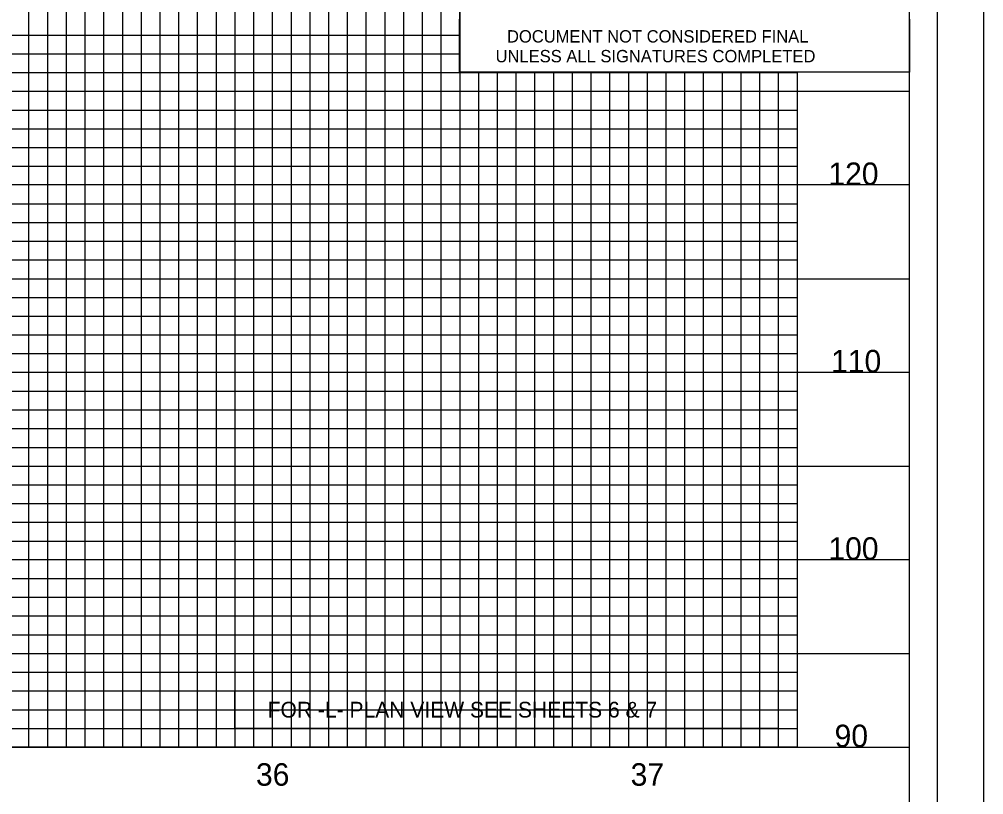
# Model space of a CAD drawing. Extents: x 2113763 to 2114783, y 714280 to 714940.
# Drawn here: x 2114525.3 to 2114782.6, y 714612.6 to 714819.5 of the extents above; entities that cross this region are included whole.
import ezdxf

# ---------------------------------------------------------------- set-up
doc = ezdxf.new("R2010")
doc.units = 0
for name, color, linetype in [('Exist Vertical Profile Horizontal Axis Label Major', 7, 'Continuous'), ('Exist Vertical Profile Vertical Axis Label', 7, 'Continuous'), ('Prop Grid Mask', 7, 'Continuous'), ('Prop PFL Text', 7, 'Continuous'), ('Sheet Cutting Line CELL', 7, 'Continuous'), ('Sheet Layout Profile Border Port 1', 7, 'Continuous'), ('Sheet Plot Border Inside CELL', 7, 'Continuous'), ('Sheet Plot Border Outside CELL', 7, 'Continuous'), ('Sheet Profile CELL', 7, 'Continuous'), ('Sheet Profile Grid Major CELL', 7, 'Continuous'), ('Sheet Profile Grid Middle CELL', 7, 'Continuous'), ('Sheet Profile Grid Minor CELL', 7, 'Continuous'), ('Sheet Sticker Exception Certification CELL', 7, 'Continuous')]:
    doc.layers.add(name, color=color, linetype=linetype)

msp = doc.modelspace()

# ---------------------------------------------------------------- linework, layer by layer
at = {"layer": 'Exist Vertical Profile Vertical Axis Label'}
msp.add_lwpolyline([(2114582.76, 714640.29), (2114727.76, 714640.29), (2114727.76, 714630.29), (2114582.76, 714630.29)], close=True, dxfattribs=at)
at = {"layer": 'Prop Grid Mask'}
msp.add_lwpolyline([(2114582.76, 714640.29), (2114727.76, 714640.29), (2114727.76, 714630.29), (2114582.76, 714630.29)], close=True, dxfattribs=at)
at = {"layer": 'Sheet Cutting Line CELL'}
msp.add_line((2114782.56, 714280.29), (2114782.56, 714940.29), dxfattribs=at)
at = {"layer": 'Sheet Layout Profile Border Port 1'}
msp.add_lwpolyline([(2113892.76, 714925.29), (2114642.73, 714925.29), (2114642.73, 714805.41), (2114732.76, 714805.29), (2114732.76, 714625.29), (2113892.76, 714625.29)], close=True, dxfattribs=at)
at = {"layer": 'Sheet Plot Border Inside CELL'}
msp.add_lwpolyline([(2113770.36, 714293.76), (2114770.26, 714293.76), (2114770.26, 714926.82), (2113770.36, 714926.82)], close=True, dxfattribs=at)
at = {"layer": 'Sheet Plot Border Outside CELL'}
msp.add_lwpolyline([(2113762.56, 714280.29), (2114782.56, 714280.29), (2114782.56, 714940.29), (2113762.56, 714940.29)], close=True, dxfattribs=at)
at = {"layer": 'Sheet Profile CELL'}
msp.add_line((2113862.76, 714625.29), (2114762.76, 714625.29), dxfattribs=at)
msp.add_lwpolyline([(2114762.76, 714925.29), (2113862.76, 714925.29), (2113862.76, 714295.29), (2114762.76, 714295.29)], close=True, dxfattribs=at)
at = {"layer": 'Sheet Profile Grid Major CELL'}
for p, q in [((2114542.76, 714925.29), (2114542.76, 714625.29)), ((2114567.76, 714925.29), (2114567.76, 714625.29)), ((2114592.76, 714925.29), (2114592.76, 714625.29)), ((2114617.76, 714925.29), (2114617.76, 714625.29)), ((2114642.76, 714925.29), (2114642.76, 714625.29)), ((2114667.76, 714805.41), (2114667.76, 714625.29)), ((2114692.76, 714805.41), (2114692.76, 714625.29)), ((2114717.76, 714805.41), (2114717.76, 714625.29)), ((2114732.76, 714805.41), (2114732.76, 714625.29)), ((2113862.76, 714800.29), (2114762.76, 714800.29)), ((2114762.76, 714775.29), (2113862.76, 714775.29)), ((2113862.76, 714750.29), (2114762.76, 714750.29)), ((2114762.76, 714725.29), (2113862.76, 714725.29)), ((2113862.76, 714700.29), (2114762.76, 714700.29)), ((2114762.76, 714675.29), (2113862.76, 714675.29)), ((2113862.76, 714650.29), (2114762.76, 714650.29))]:
    msp.add_line(p, q, dxfattribs=at)
at = {"layer": 'Sheet Profile Grid Middle CELL'}
for p, q in [((2113892.76, 714815.29), (2114642.76, 714815.29)), ((2113892.76, 714810.29), (2114642.76, 714810.29)), ((2113892.76, 714805.29), (2114732.76, 714805.29)), ((2113892.76, 714795.29), (2114732.76, 714795.29)), ((2113892.76, 714790.29), (2114732.76, 714790.29)), ((2113892.76, 714785.29), (2114732.76, 714785.29)), ((2113892.76, 714780.29), (2114732.76, 714780.29)), ((2113892.76, 714770.29), (2114732.76, 714770.29)), ((2113892.76, 714765.29), (2114732.76, 714765.29)), ((2113892.76, 714760.29), (2114732.76, 714760.29)), ((2113892.76, 714755.29), (2114732.76, 714755.29)), ((2113892.76, 714745.29), (2114732.76, 714745.29)), ((2113892.76, 714740.29), (2114732.76, 714740.29)), ((2113892.76, 714735.29), (2114732.76, 714735.29)), ((2113892.76, 714730.29), (2114732.76, 714730.29)), ((2113892.76, 714720.29), (2114732.76, 714720.29)), ((2113892.76, 714715.29), (2114732.76, 714715.29)), ((2113892.76, 714710.29), (2114732.76, 714710.29)), ((2113892.76, 714705.29), (2114732.76, 714705.29)), ((2113892.76, 714695.29), (2114732.76, 714695.29)), ((2113892.76, 714690.29), (2114732.76, 714690.29)), ((2113892.76, 714685.29), (2114732.76, 714685.29)), ((2113892.76, 714680.29), (2114732.76, 714680.29)), ((2113892.76, 714670.29), (2114732.76, 714670.29)), ((2113892.76, 714665.29), (2114732.76, 714665.29)), ((2113892.76, 714660.29), (2114732.76, 714660.29)), ((2113892.76, 714655.29), (2114732.76, 714655.29)), ((2113892.76, 714645.29), (2114732.76, 714645.29)), ((2113892.76, 714640.29), (2114732.76, 714640.29)), ((2113892.76, 714635.29), (2114732.76, 714635.29)), ((2113892.76, 714630.29), (2114732.76, 714630.29))]:
    msp.add_line(p, q, dxfattribs=at)
msp.add_lwpolyline([(2114657.76, 714790.29), (2114732.76, 714790.29)], dxfattribs=at)
at = {"layer": 'Sheet Profile Grid Minor CELL'}
for p, q in [((2114527.76, 714925.29), (2114527.76, 714625.29)), ((2114532.76, 714925.29), (2114532.76, 714625.29)), ((2114537.76, 714925.29), (2114537.76, 714625.29)), ((2114547.76, 714925.29), (2114547.76, 714625.29)), ((2114552.76, 714925.29), (2114552.76, 714625.29)), ((2114557.76, 714925.29), (2114557.76, 714625.29)), ((2114562.76, 714925.29), (2114562.76, 714625.29)), ((2114572.76, 714925.29), (2114572.76, 714625.29)), ((2114577.76, 714925.29), (2114577.76, 714625.29)), ((2114582.76, 714925.29), (2114582.76, 714625.29)), ((2114587.76, 714925.29), (2114587.76, 714625.29)), ((2114597.76, 714925.29), (2114597.76, 714625.29)), ((2114602.76, 714925.29), (2114602.76, 714625.29)), ((2114607.76, 714925.29), (2114607.76, 714625.29)), ((2114612.76, 714925.29), (2114612.76, 714625.29)), ((2114622.76, 714925.29), (2114622.76, 714625.29)), ((2114627.76, 714925.29), (2114627.76, 714625.29)), ((2114632.76, 714925.29), (2114632.76, 714625.29)), ((2114637.76, 714925.29), (2114637.76, 714625.29)), ((2114647.76, 714805.41), (2114647.76, 714625.29)), ((2114652.76, 714805.41), (2114652.76, 714625.29)), ((2114657.76, 714805.41), (2114657.76, 714625.29)), ((2114662.76, 714805.41), (2114662.76, 714625.29)), ((2114672.76, 714805.41), (2114672.76, 714625.29)), ((2114677.76, 714805.41), (2114677.76, 714625.29)), ((2114682.76, 714805.41), (2114682.76, 714625.29)), ((2114687.76, 714805.41), (2114687.76, 714625.29)), ((2114697.76, 714805.41), (2114697.76, 714625.29)), ((2114702.76, 714805.41), (2114702.76, 714625.29)), ((2114707.76, 714805.41), (2114707.76, 714625.29)), ((2114712.76, 714805.41), (2114712.76, 714625.29)), ((2114722.76, 714805.41), (2114722.76, 714625.29)), ((2114727.76, 714805.41), (2114727.76, 714625.29))]:
    msp.add_line(p, q, dxfattribs=at)
at = {"layer": 'Sheet Sticker Exception Certification CELL'}
for p, q in [((2114642.73, 714805.41), (2114642.73, 714819.51)), ((2114762.76, 714819.5), (2114762.76, 714805.4)), ((2114762.76, 714805.41), (2114642.73, 714805.41))]:
    msp.add_line(p, q, dxfattribs=at)

# ---------------------------------------------------------------- texts
at = {"layer": 'Exist Vertical Profile Horizontal Axis Label Major'}
for s, p in [('36', (2114588.4, 714615)), ('36', (2114588.4, 714615)), ('36', (2114588.4, 714615)), ('36', (2114588.4, 714615)), ('36', (2114588.4, 714615)), ('36', (2114588.4, 714615)), ('37', (2114688.36, 714615)), ('37', (2114688.36, 714615)), ('37', (2114688.36, 714615)), ('37', (2114688.36, 714615)), ('37', (2114688.36, 714615)), ('37', (2114688.36, 714615))]:
    msp.add_text(s, height=6, dxfattribs=at).set_placement(p)
at = {"layer": 'Exist Vertical Profile Vertical Axis Label'}
for s, p in [('120', (2114741.12, 714775.29)), ('110', (2114741.84, 714725.29)), ('100', (2114741.12, 714675.29)), ('90', (2114742.78, 714625.29))]:
    msp.add_text(s, height=6, dxfattribs=at).set_placement(p)
at = {"layer": 'Prop PFL Text'}
msp.add_text('FOR -L- PLAN VIEW SEE SHEETS 6 & 7', height=4.2, dxfattribs=at).set_placement((2114591.51, 714633.19))
at = {"layer": 'Sheet Sticker Exception Certification CELL'}
for s, p in [('DOCUMENT NOT CONSIDERED FINAL', (2114655.38, 714813.3)), ('UNLESS ALL SIGNATURES COMPLETED', (2114652.33, 714808.02))]:
    msp.add_text(s, height=3.3, rotation=0, dxfattribs=at).set_placement(p)

doc.saveas('drawing.dxf')
